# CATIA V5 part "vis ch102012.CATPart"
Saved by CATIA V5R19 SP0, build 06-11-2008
Part number: vis CH102010
Bounding box of the stored display mesh (mm): x 0 to 12, y -1.9 to 1.9, z -1.9 to 1.9
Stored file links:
  I:\mediator\vis ch102012.CATPart
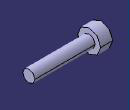
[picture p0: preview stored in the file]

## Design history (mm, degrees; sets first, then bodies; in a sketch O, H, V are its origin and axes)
Body1 (main body)
  Sketch1 on yz-plane, origin (0, 0, 0), H (0, 1, 0), V (0, 0, 1)
    circle A1 centre (0, 0) radius 1.9
    radius A1 = 1.9
  Pad1: profile Sketch1, direction (1, 0, 0), length 2
  Sketch2 on end face of Pad1, origin (2, 0, 0), H (0, 1, 0), V (0, 0, 1)
    circle A1 centre (0, 0) radius 1
    radius A1 = 1
  Pad2: profile Sketch2, direction (1, 0, 0), length 10
  Sketch3 on start face of Pad1, origin (0, 0, 0), H (0, -1, 0), V (0, 0, 1)
    axis line L1 (0, 1.0166) -> (0, -1.3601)
    point P1 (0, 1.0166)
    point P3 (0.5398, 0.5207)
    line L2 (0.5398, 0.5207) -> (0.5398, -0.5207)
    point P4 (0.5398, -0.5207)
    line L3 (0.5398, -0.5207) -> (0, -0.75)
    point P5 (0, -0.75)
    point P6 (0.5398, 0.5207)
    line L4 (0.5398, 0.5207) -> (0, 0.75)
    point P7 (0, 0.75)
    point P8 (-0.5398, -0.5207)
    point P9 (-0.5398, 0.5207)
    line L5 (-0.5398, 0.5207) -> (-0.5398, -0.5207)
    point P10 (0, 0.75)
    point P11 (-0.5398, 0.5207)
    line L6 (-0.5398, 0.5207) -> (0, 0.75)
    point P12 (0, -0.75)
    line L7 (-0.5398, -0.5207) -> (0, -0.75)
    coincidence: P1 V, P5 L1, P7 L1, P3 P6, P5 P12, P7 P10, P9 P11
    vertical: L1 V, L2 V
    symmetry: P4 P8 L1, P3 P9 L1, L2 L5 L1, P7 P10 L1, P6 P11 L1, L4 L6 L1, P5 P12 L1, L3 L7 L1
  Pocket1: profile Sketch3, direction (1, 0, 0), length 1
